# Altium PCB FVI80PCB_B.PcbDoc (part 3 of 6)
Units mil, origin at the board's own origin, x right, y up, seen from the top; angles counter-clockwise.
Board outline 3540 x 3115 mil, 12 copper layers (Top Layer, Int1(GND), Int2(Signal), Int3(GND), Int4(Signal), Int5 (GND&PW), Int6 (GND&PW), Int7(Signal), Int8(GND), Int9(Signal), Int10(GND), Bottom Layer), stack 77.136 mil thick; 488 components, 321 nets, 1809 pads, 882 vias.
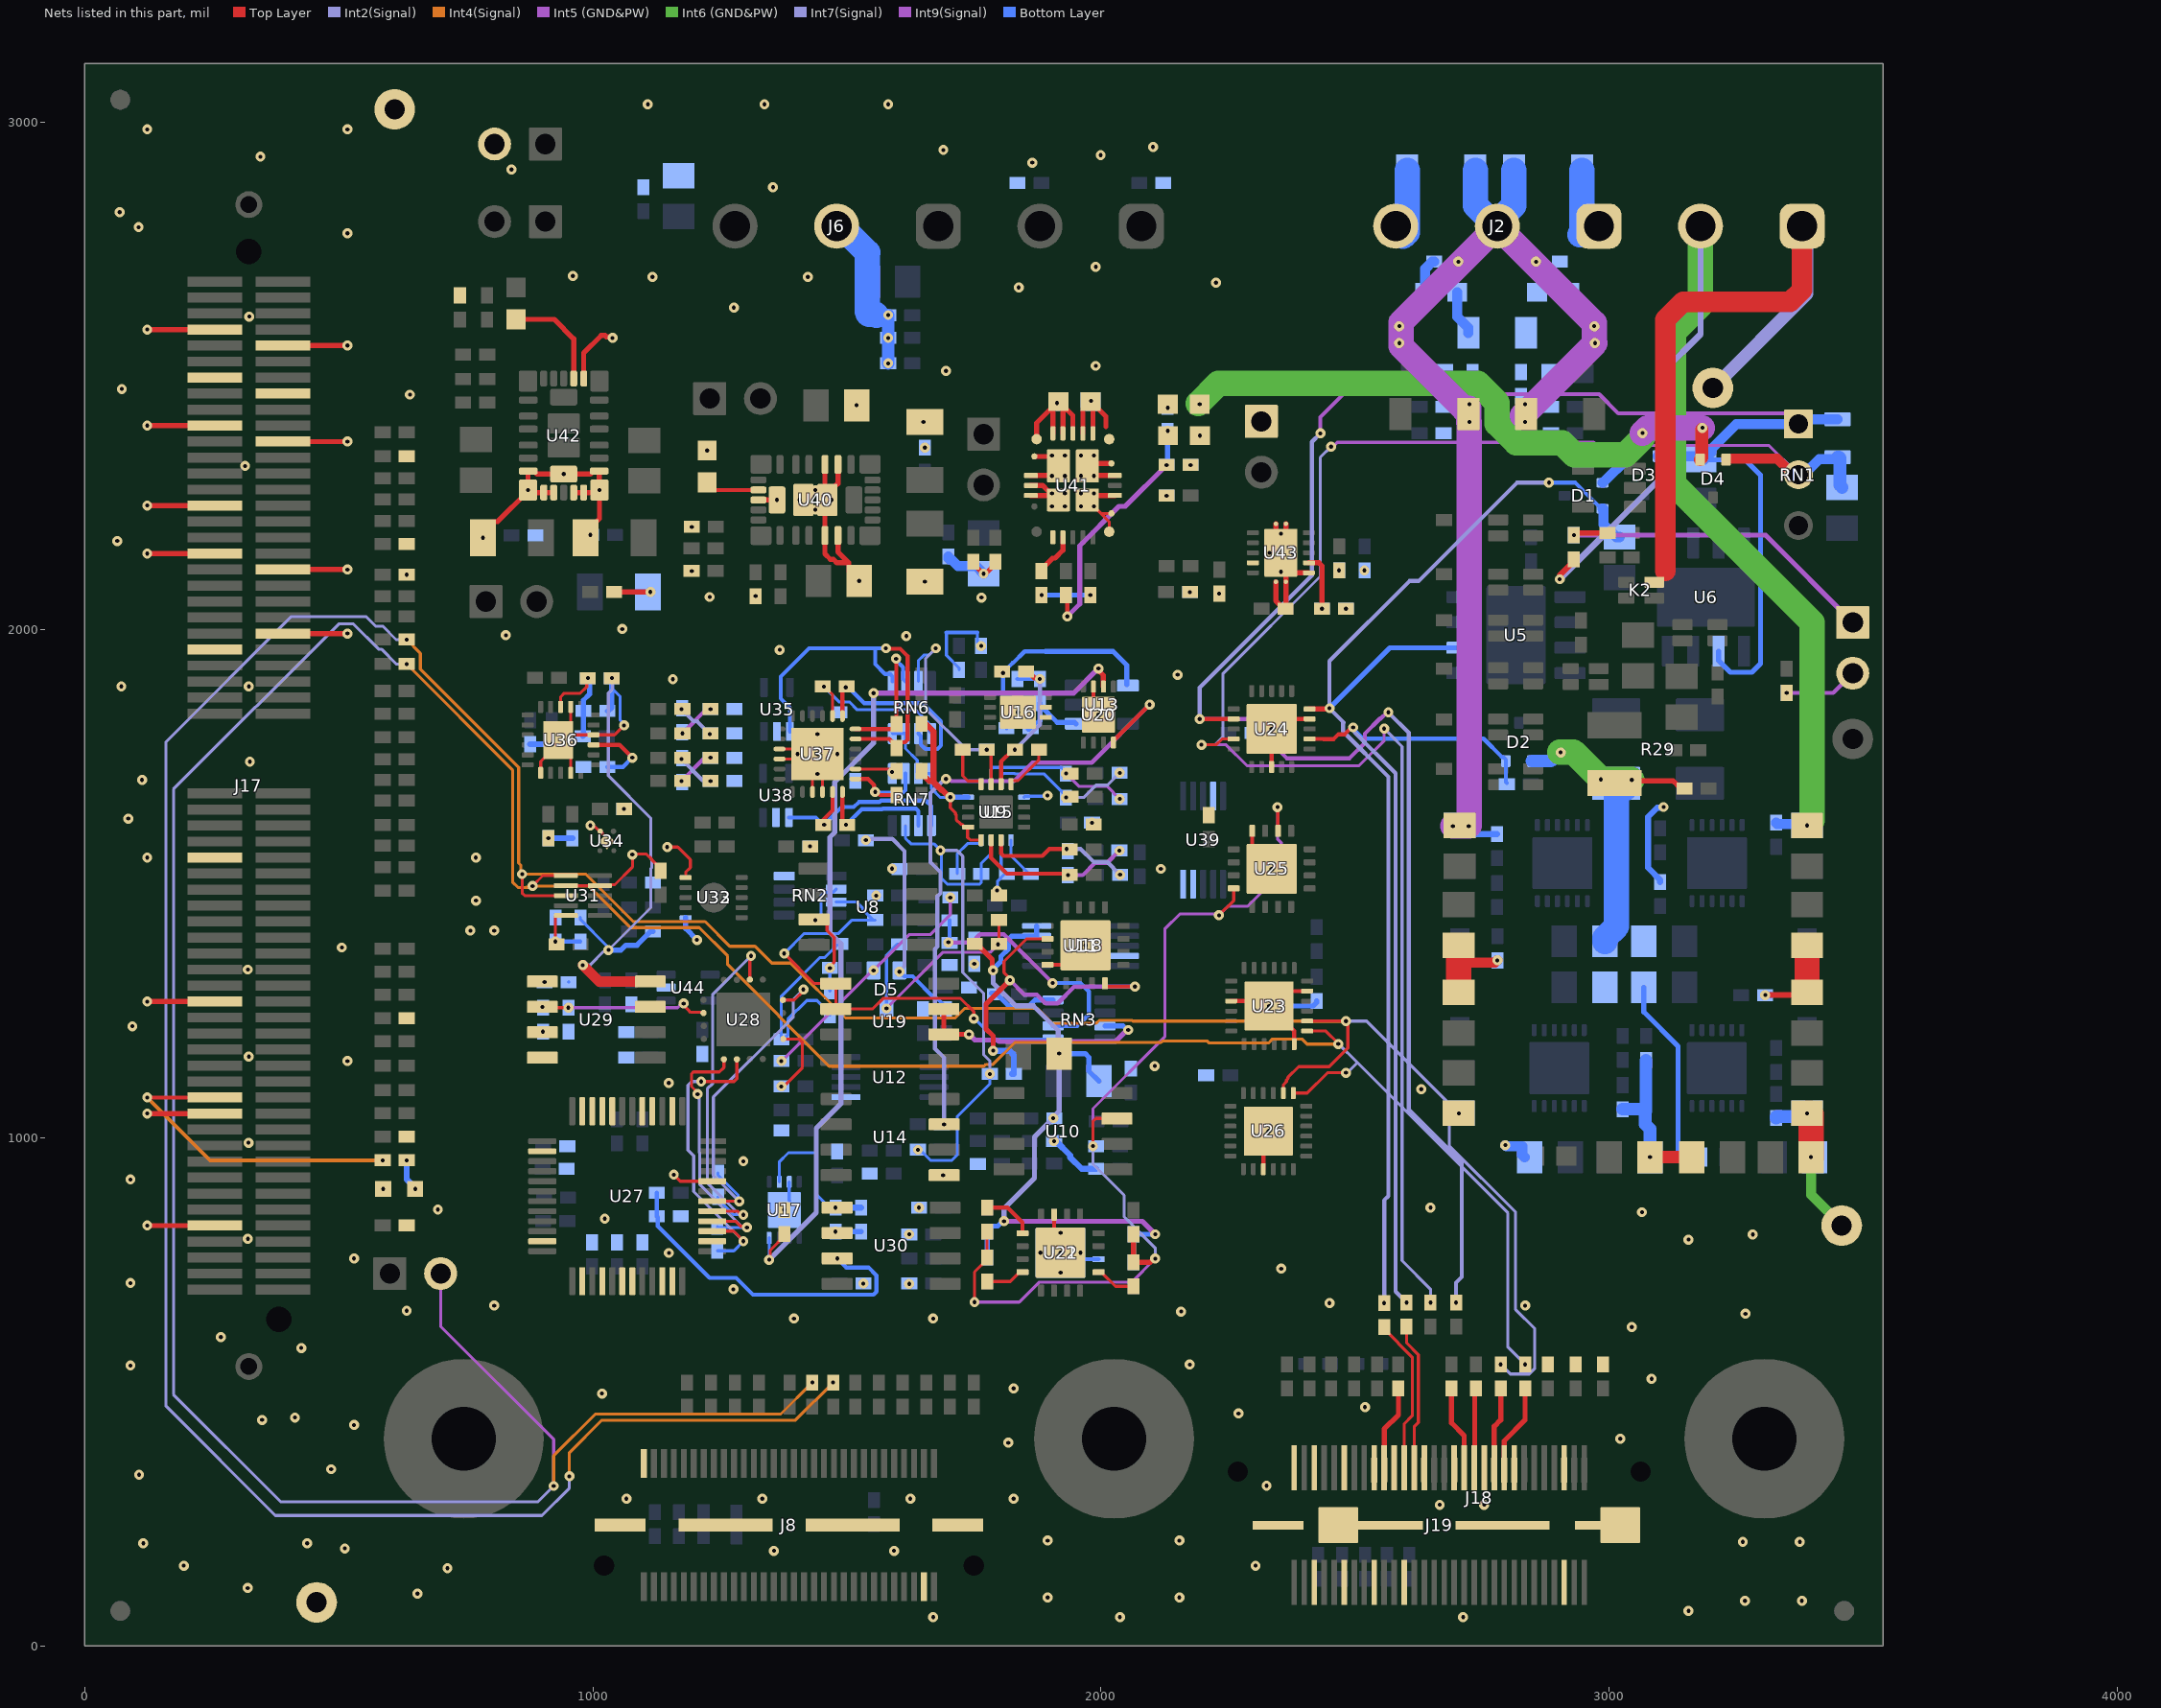
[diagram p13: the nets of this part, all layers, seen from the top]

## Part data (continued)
U24: library part CMP-0120407-1, "36 V, Low Ron, 2:1, 4 Channel Precision Switches with 1.8 V Logic", Digikey Part Number=296-TMUX6234RRQRCT-ND, Manufacturer="Texas Instruments", Max Supply Voltage=36V, Min Supply Voltage=4.5V, Mouser Part Number=595-TMUX6234RRQR, Nominal Supply Current=65uA, On State Resistance=3.6Ω, Operating Temperature Range="-40°C to +125°C"
U27: library part CMP-0093014-3, "20-Bit, Low-Noise, Ultra-Low Harmonic Distortion, FastSettling, High-Voltage Output, Digital-to-Analog Converter (DAC), TQFP48", Manufacturer="Texas Instruments", Max Supply Voltage=5.5V, Min Supply Voltage=1.7V, Operating Temperature Range="-40°C to +125°C"
U28: library part CMP-0126090-1, "Zero-Drift Amplifier 4 Circuit Rail-to-Rail 16-WQFN (4x4)", Input Bias Current=100pA, Input Offset Voltage=1uV, Manufacturer="Texas Instruments", Max Dual Supply Voltage=18V, Max Supply Voltage=36V, Min Dual Supply Voltage=2.25V, Min Supply Voltage=4.5V, Mouser Part Number=595-OPA4187IRUMR, Nominal Supply Current=100uA, Operating Temperature Range="-40°C to +125°C", Output Current Per Channel=30mA, Voltage Gain=160dB
U29: library part CMP-0123003-1, "0.8ppm/°C drift (max), 0.11ppmp-p 1/f noise, 380μA current precision voltage reference", Digikey Part Number=296-REF54410CDRTR-ND, Manufacturer="Texas Instruments", Max Supply Voltage=18V, Min Supply Voltage=4.346V, Mouser Part Number=595-REF54410CDR, Nominal Supply Current=260uA, Operating Temperature Range="0°C to +70°C", Output Voltage=4.096V
U31: library part CMP-0860933-1, "DAC80502DRX, DRX0010A (WSON-10)", Alternate Manufacturer="Texas Instruments"
U32 U33: library part CMP-0126256-1, "High-precision (40µV offset), 2-MHz, 88dB CMRR, low-power, e-trim difference amplifier 10-VSON -40 to 125", Digikey Part Number=296-INA592IDRCRTR-ND, Input Offset Voltage=14uV, Manufacturer="Texas Instruments", Max Dual Supply Voltage=18V, Max Supply Voltage=36V, Min Dual Supply Voltage=2.25V, Min Supply Voltage=4.5V, Mouser Part Number=595-INA592IDRCR, Nominal Supply Current=1.1mA, Operating Temperature Range="-40°C to +125°C", Output Current Per Channel=65mA, Voltage Gain=1/2V/V
U34: library part CMP-0123489-1, "Linear Voltage Regulator IC Positive Fixed 1 Output 300mA 4-X2SON (1x1)", Digikey Part Number=296-TPS7A2018PDQNRCT-ND, Dropout Voltage=200mV, Manufacturer="Texas Instruments", Max Supply Voltage=6V, Min Supply Voltage=2.1V, Mouser Part Number=595-TPS7A2018PDQNR, Nominal Supply Current=6.5uA, Operating Temperature Range="-40°C to +125°C", Output Voltage=1.8V
U35 U38 U44: library part CMP-0126581-1, "Standard (General Purpose) Amplifier 1 Circuit Push-Pull, Rail-to-Rail SC-70-5", Digikey Part Number=296-OPA397DCKRCT-ND, Input Bias Current=0.01pA, Input Offset Voltage=10uV, Manufacturer="Texas Instruments", Max Dual Supply Voltage=2.75V, Max Supply Voltage=5.5V, Min Dual Supply Voltage=850mV, Min Supply Voltage=1.7V, Mouser Part Number=595-OPA397DCKR, Nominal Supply Current=1.22mA, Operating Temperature Range="-40°C to +125°C", Output Current Per Channel=65mA, Voltage Gain=132dB
U36: library part CMP-0121626-2, "Dual, Simultaneous-Sampling, 16-Bit, 5 MSPS SAR ADC, VQFN-HR22", Manufacturer="Texas Instruments", Max Supply Voltage=5.25V, Min Supply Voltage=1.75V, Operating Temperature Range="-40°C to +125°C"
U37: library part CMP-0014032-1, "Low-Noise, Precision, 150-MHz, Fully Differential Amplifier, RTW0024A (WQFN-24)", Alternate Manufacturer="Texas Instruments", Alternate PartNumber=THS4552IRTWT
U40 U42: library part CMP-0090663-2, "TPSM63603 Cruzline Power Module", Manufacturer="Texas Instruments", Max Supply Voltage=36V, Min Supply Voltage=3V, Nominal Supply Current=9uA, Operating Temperature Range="-40°C to +125°C", Output Voltage=1-12V, Switching Frequency=200-2200kHz
U41: library part CMP-0094706-3, "3-V to 17-V, 2-A Low Noise and Low Ripple Buck Converter Module with Integrated Ferrite Bead Filter Compensation", Manufacturer="Texas Instruments", Max Supply Voltage=17V, Min Supply Voltage=3V, Nominal Supply Current=5mA, Operating Temperature Range="-55°C to +125°C", Output Voltage=0.8-5.5V, Switching Frequency=1/2.2MHz
U43: library part CMP-0091022-1, "1-A, Ultra-Low Noise, Ultra-High PSRR, RF Voltage Regulator", Dropout Voltage=210mV, Manufacturer="Texas Instruments", Max Supply Voltage=5.5V, Min Supply Voltage=1.7V, Nominal Supply Current=15-47mA, Operating Temperature Range="-40°C to +150°C", Output Voltage=0.4-5.3V

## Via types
v1: diameter 19.68, hole 7.87, Top Layer to Bottom Layer, tented both sides, 834 vias
v2: diameter 19.68, hole 7.87, Top Layer to Bottom Layer, 39 vias
v3: diameter 23.62, hole 11.81, Top Layer to Bottom Layer, tented both sides, 5 vias
v4: diameter 19.68, hole 7.87, Top Layer to Bottom Layer, tented bottom, 4 vias

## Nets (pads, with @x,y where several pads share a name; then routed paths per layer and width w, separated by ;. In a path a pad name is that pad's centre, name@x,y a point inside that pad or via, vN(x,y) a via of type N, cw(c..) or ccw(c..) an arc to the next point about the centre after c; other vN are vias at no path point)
ClampH_s: D5.1 R49.2 R67.2 | length 485.5
  Int9(Signal) w6: v1(1371.16,1151.5) 1372.61,1151.5 1551.05,1329.93 v1(1552.5,1329.93) 1623.23,1400.67 1664.83,1400.67 1703.62,1439.46 v1(1703.62,1473.26)
ClampL_s: D5.2 R63.2 R76.2 | length 451.2
  Int2(Signal) w8: v1(1537.66,1586.4) 1540.82,1586.4 1543.26,1588.84 1589.6,1588.84 1613.52,1564.92 1613.52,1337.98 1603.68,1328.13 v1(1603.68,1327.45)
  Bottom Layer w8: v1(1603.68,1327.45) 1612.98,1318.15 1629.53,1318.15 1673.49,1274.19 1678.37,1274.19 1695,1257.56 R76.2@1695,1255
ClampSignal: R64.2 RN2.3 RN3.5 U19.1 U19.2 | length 953.2
  Top Layer w6: v1(1376.75,1363.11) 1435.83,1304.02 U19.1@1478.24,1304.02 U19.2@1478.24,1254.02 1550.33,1254.02 1571.14,1274.83 1723.9,1274.83 1750,1248.73 v1(1750,1235) v1@1750,1230
  Bottom Layer w6: v1(1376.75,1363.11) 1416.17,1402.53 1483.85,1402.53 1510.42,1429.1 R64.2@1551.88,1429.1 ; RN2.3@1479.01,1464.4 1519.39,1464.4 1531.23,1452.56 1531.23,1449.75 R64.2@1551.88,1429.1 ; R64.2@1555.82,1429.1 R64.2@1551.88,1429.1 ; v1@1751.11,1236.11 1792.24,1194.99 RN3.5@1905.83,1194.99
Current-: R61.1 U14.7 U20.8 | length 1285.7
  Top Layer w8: U20.8@2024.73,1778.29 2024.73,1785.18 2025.65,1786.1 2028.81,1786.1 2095.71,1853 v1(2096,1853)
  Int2(Signal) w8: v1(1691.55,1026.72) 1691.55,1158.04 1673.54,1176.06 1673.54,1372.14 1678.19,1376.8 1678.19,1475.88 1684.29,1481.98 1684.29,1522.92 1664.44,1542.76 1664.44,1678.73 1692.56,1706.84 v1(1695.24,1706.84)
  Int9(Signal) w8: v1(1695.24,1706.84) 1697.47,1704.6 1703.71,1704.6 1705.76,1702.55 1829.04,1702.55 1865.5,1739 1982,1739 v1(2096,1853)
DA1+: C37.2 U15.9 | length 97.3
  Top Layer w6: U15.9@1823.32,1696.64 1823.32,1701.56 1825.24,1703.48 1837.26,1703.48 1878.07,1744.29 C37.2@1878.07,1764.22
DA1-: C36.2 U15.12 | length 96.4
  Top Layer w6: C36.2@1728.2,1764.22 1728.2,1713.02 1738.67,1702.55 1762.34,1702.55 1764.26,1700.62 U15.12@1764.26,1696.64
DA2+: C28.2 U9.9 | length 84.5
  Bottom Layer w6: U9.9@1823.32,1586.4 1823.32,1555.25 1858.23,1520.34 C28.2@1862.17,1520.34
DA2-: C19.2 U9.12 | length 100.2
  Bottom Layer w6: C19.2@1717.35,1520.34 1717.35,1559.58 1737.33,1579.56 1762.34,1579.56 1764.26,1581.48 U9.12@1764.26,1586.4
Error: R54.2 R80.2 R82.2 R86.1 R107.1 R108.1 R109.1 R112.2 U11.9 U11.10 | length 1450.8
  Top Layer w10: R54.2@1752.09,1381.72 1756.02,1381.72 1786.19,1351.55 1786.19,1331.79 v1(1788.05,1329.93)
  Int2(Signal) w10: v1(1788.05,1329.93) 1788.05,1304.6 1832.36,1260.28 1867,1260.28 1916.11,1211.18 1916.11,1167.94 v1(1917.96,1166.09) 1917.96,1053.2 1906.33,1041.57 v1(1906.33,1038.95) 1869.22,1001.83 1869.22,921.22 1809.5,861.5 v1(1809.5,836.18)
  Int9(Signal) w10: v1(1809.5,836.18) 2081.39,836.18 v1(2107.06,810.51)
  Bottom Layer w10: R109.1@1776.09,764.9 1776.26,765.06 1776.26,815.53 R108.1@1776.42,815.69 1776.42,819.63 1783.23,826.44 1797.13,826.44 1806.88,836.18 v1(1809.5,836.18) ; v1(1788.05,1329.93) 1788.05,1332.55 1803.35,1347.86 1803.35,1357.54 1818.2,1372.4 1818.2,1391.12 1824.06,1396.98 1872.68,1396.98 U11.9@1873.59,1397.89 U11.10@1873.59,1417.57 ; v1(1917.96,1166.09) 1969.18,1166.09 1976.48,1158.78 1976.48,1131.78 R80.2@1996.48,1111.78 ; R112.2@2064.51,755.52 R107.1@2064.51,810.55 2064.55,810.51 v1(2107.06,810.51)
Force_signal_external_Sh: J18.2 J19.20 R198.2 | length 167.9
  Top Layer w10: J19.20@2557.73,350.8 2557.73,427.12 2585.62,455 R198.2@2585.62,507.1
GangForce: R100.2 U17.8 U20.2 | length 1827.3
  Top Layer w6: v1(1347.22,760.3) 1349.27,762.36 1349.27,779.15 1377.4,807.27 R100.2@1377.4,811.21
  Top Layer w10: v1(1995.2,1924.23) 1995.2,1920.53 2005.05,1910.69 U20.2@2005.05,1888.53
  Int2(Signal) w10: v1(1347.22,760.3) 1439.91,853 1439.91,1019.03 1488.23,1067.34 1488.23,1383.12 1466.8,1404.56 1466.8,1592.26 1476.19,1601.65 1476.19,1700.78 1552.5,1777.09 v1(1552.5,1875.84)
  Int9(Signal) w10: v1(1552.5,1875.84) 1946.81,1875.84 v1(1995.2,1924.23)
  Bottom Layer w6: v1(1347.22,760.3) U17.8@1347.22,803.34
GNDA: C1.1 C2.1 C3.1 C4.1 C5.1 C6.1 C7.1 C8.1 C9.2 C10.2 C11.2 C12.2 C13.2 C14.1 C15.1 C16.1 C17.1 C18.1 C140.2 C141.2 C142.1 C143.1 J1.2 J2.2 R4.1 R5.1 R6.1 R12.1 R13.1 R14.1 R15.1 R16.1 R17.1 R32.1 R72.1 R73.1 R74.1 R85.1 R96.1 R97.1 R98.1 R101.1 R102.1 TP3.1 | length 5640.5
  Top Layer w12: v1(2903,2100) 2904.47,2101.47 2904.47,2108.91 2931,2135.44 R32.1@2931,2139.38 ; v1(3307.62,1281.42) 3384.45,1281.42 R12.1@3390,1286.97
  Top Layer w20: 2704.42,1345.16 2775.84,1345.16 v1(2780.34,1349.66)
  Top Layer w25: v1(3080.72,962.37) R16.1@3163.34,962.37
  Top Layer w50: R85.1@2704.42,1286.97 2704.42,1345.16 R101.1@2704.42,1379.16 ; v1(3390,1048.52) 3396.5,1048.52 3397.81,1047.21 v1(3397.81,962.37) ; R12.1@3390,1286.97 R73.1@3390,1379.16
  Int5 (GND&PW) w50: v1(2692.82,1614) v1(2724,1614) ; 2715,2435 2591,2559 2591,2605.66 J2.2@2780.34,2795 2971,2604.34 v1@2971,2564.69 ; v1@2724,2409.48 v1@2724,2436 ; v1@2725.28,1615.28 v1(2725.28,2409.48) ; 2830,2422.17 v1(2972.52,2564.69)
  Int6 (GND&PW) w20: v1(3397.81,962.37) 3397.81,888.13 TP3.1@3458.22,827.72
  Int6 (GND&PW) w50: J1.2@3180,2795 3180,2639.06 3127,2586.06 3127,2288 3400,2015 3400,1625.25 v1(3390,1615.25)
  Int2(Signal) w12: v1(2903,2100) 3107,2304 3107,2509 3180.34,2582.34 J1.2@3180.34,2795
  Bottom Layer w12: R102.1@2715.79,1605.79 2723.46,1598.12 C4.1@2779.54,1598.12 ; C2.1@3100.81,1504.08 3100.81,1508.02 3077,1531.83 3077,1632.03 3095.07,1650.1 3106.03,1650.1 v1(3107.5,1651.57)
  Bottom Layer w20: v1(2796,986) 2798.13,983.87 2829.37,983.87 2829.37,966.63 R6.1@2834,962 ; C8.1@3329,1620.62 3329,1619.74 3330.81,1617.93 3387.31,1617.93 v1(3390,1615.25)
  Bottom Layer w25: C7.1@3027,1056.69 3073,1056.69 ; C5.1@3073,1153.38 3073,1056.69 ; v1(3080.72,962.37) 3080.72,1017.77 3071.48,1027.01 3071.48,1050.49 3073,1052.01 3073,1056.69 ; C3.1@3329,1039.2 3329,1041.76 3329.69,1042.44 3383.93,1042.44 v1(3390,1048.52)
  Bottom Layer w50: C14.1@2736.93,2905 2736.93,2836.07 2777.99,2795 J2.2@2780.34,2795 2780.34,2803.34 2813.07,2836.07 C9.2@2813.07,2905
  other v1: 2704.42,1048.52 2834.72,2409.48 2725.28,2444.25 2834.72,2444.25 2587.48,2564.69 2587.48,2598.15 2971,2598.15 2703.62,2725 2856.38,2725
GNDB: C20.1 C21.1 C22.1 C23.1 C24.1 C25.1 C26.1 C28.1 C29.2 C31.2 C32.1 C33.2 C34.2 C35.1 C42.1 C43.1 C44.1 C45.2 C47.2 C48.1 C49.1 C50.2 C51.2 C53.1 C54.2 C55.1 C57.1 C58.2 C59.1 C60.1 C61.1 C62.1 C63.1 C64.1 C65.2 C66.2 C67.2 C68.2 C69.2 C70.2 C71.1 C72.1 C75.2 C76.1 C77.2 C78.1 C79.2 C80.1 C85.1 C86.2 C88.1 C89.1 C90.2 C91.2 C92.1 C93.2 C95.2 C97.1 C99.2 C100.2 C101.2 C102.2 C103.2 C104.2 C105.2 C106.2 C107.2 C108.2 C109.2 C110.2 C111.2 C112.2 C113.2 C114.2 C115.2 C116.2 C117.2 C118.2 C119.2 C120.1 C122.1 C123.1 C124.1 C125.1 C126.1 C127.1 C128.2 C129.2 C130.2 C131.2 C132.1 C133.2 C134.1 C137.2 C138.2 C139.2 C144.1 C145.1 C146.1 C147.1 C148.2 C149.2 C150.2 D1.1 D2.1 D3.1 D4.2 D8.1 J5.2 J6.2 J7.2 J8.3 J8.60 J8.MP1 J8.MP2 J8.MP3 J8.MP4 J17.7 J17.10 J17.13 J17.16 J17.19 J17.22 J17.29 J17.35 J17.38 J17.46 J17.47 J17.65 J17.83 J17.97 J17.111 J18.1 J18.3 J18.6 J18.9 J18.12 J18.15 J18.20 J18.MP1 J18.MP2 J19.2 J19.5 J19.6 J19.11 J19.12 J19.17 J19.18 J19.22 J19.23 J19.28 J19.34 J19.40 J19.46 J19.55 J19.56 J19.MP1 J19.MP2 J19.MP3 J19.MP4 R1.2 R2.2 R8.2 R18.2 R19.2 R24.1 R27.2 R29.I2 R48.1 R57.1 R66.2 R69.2 R70.2 R77.2 R78.2 R79.1 R90.1 R100.1 R104.1 R110.1 R113.2 R122.2 R127.1 R142.1 R149.1 R150.2 R152.2 R153.2 R154.1 R156.2 R158.2 R161.1 R164.1 R168.1 R234.2 RN2.8 RN3.8 RN6.7 RN6.8 RN7.7 RN7.8 TP5.1 TP6.1 U9.5 U9.10 U9.16 U11.4 U12.1 U14.5 U15.1 U15.16 U16.2 U16.3 U16.9 U17.3 U17.9 U18.4 U18.17 U20.3 U20.9 U21.3 U21.17 U22.3 U22.17 U23.9 U23.18 U23.23 U23.25 U24.4 U24.18 U24.21 U25.4 U25.17 U26.9 U26.25 U27.2 U27.8 U27.14 U27.16 U27.17 U27.20 U27.21 U27.22 U27.23 U27.26 U27.35 U27.38 U27.40 U27.42 U27.43 U27.46 U27.47 U28.9 U29.3 U29.4 U29.7 U29.8 U31.4 U31.7 U32.6 U33.6 U34.2 U34.5 U35.2 U36.4 U36.8 U36.18 U36.21 U36.23 U37.15 U37.16 U37.21 U37.22 U37.25 U38.2 U39.4 U39.9 U39.10 U40.5 U40.6 U40.16 U40.17 U40.24 U40.27 U40.28 U40.29 U41.1 U41.2 U41.3 U41.5 U41.6 U41.7 U41.8 U41.9 U41.16 U41.17 U41.20 U41.25 U41.26 U41.28 U42.7 U42.8 U42.9 U42.10 U42.12 U42.13 U42.14 U42.15 U42.22 U42.30 U43.4 U43.6 U43.11 U44.2 | length 11472
  Top Layer w6: U36.18@897.43,1718.68 897.43,1741.34 931.96,1775.87 U36.23@931.96,1783.64 ; U31.7@946.9,1496.88 U31.4@1013.83,1496.88 1015.56,1498.6 1043.47,1498.6 1078.17,1533.31 1078.17,1557.38 v1(1077.72,1557.83) 1078.92,1559.03 1105.21,1559.03 1116.25,1547.99 1116.25,1547.04 1133.43,1529.86 C62.1@1133.43,1525.93 ; U36.21@956.48,1718.68 956.45,1759.15 U36.23@931.96,1783.64 ; U36.8@956.48,1848.6 956.45,1808.13 U36.23@941.8,1793.48 ; v1(995.22,1615.08) 997.84,1612.46 1004.65,1612.46 1013.41,1603.7 U34.2@1014.76,1603.7 1027.76,1590.71 U34.5@1027.76,1583.82 ; v1(1061.52,1812.34) 1042.66,1793.48 U36.4@1001.76,1793.48 U36.23@941.8,1793.48 ; v1(1146.44,1572.74) 1167.17,1572.74 1191.92,1547.99 1191.92,1532.38 1182.81,1523.26 U33.6@1182.81,1512.63 ; v1(1159.41,927.72) 1172.21,914.92 U27.8@1235.2,914.92 ; U37.16@1367.46,1746.13 1432.42,1746.13 v2(1442.27,1755.97) ; U37.15@1367.46,1765.81 1394.09,1765.81 1402.9,1757 v2(1402.9,1755.97) ; v1@1374.11,1100.14 1412.74,1138.77 1412.74,1187.65 1405.41,1194.99 U28.9@1374.82,1194.99 ; U37.21@1432.42,1681.17 1432.42,1707.79 1441.24,1716.6 v2(1442.27,1716.6) 1443.3,1716.6 1452.11,1707.79 U37.22@1452.11,1681.17 ; v1(1703.62,1671.05) 1703.62,1649.94 1714.08,1639.48 1714.08,1637.07 1715.26,1635.89 1715.26,1626.78 1724.29,1617.76 1726.02,1617.76 1731.78,1611.99 U15.16@1738.67,1611.99 1737.69,1611.01 1737.69,1591.69 1742.97,1586.4 U15.1@1764.26,1586.4 ; U41.25@1973.55,2256.04 v1(1986.34,2243.25) 2000.12,2229.47 ; U41.1@2016.43,2193.48 2016.43,2213.17 2000.12,2229.47 ; U41.2@2020.79,2229.47 2000.12,2229.47 ; U36.23@931.96,1783.64 U36.23@941.8,1793.48
  Top Layer w8: U18.4@1895,1340.8 1931.42,1340.8 v1(1969.8,1379.19) ; U22.3@1907.84,849.01 1907.84,819.42 1913.68,813.58 v1(1920.63,813.58) ; U20.3@1985.36,1888.53 1985.36,1843.25 v1(1995.2,1833.41) ; U23.9@2256.48,1269.61 2321.44,1269.61 v1(2331.28,1259.76) ; U25.4@2297.8,1604.61 2297.8,1568.19 v1(2336.19,1529.81) ; U26.9@2319.86,938.75 2319.86,1003.71 v1(2329.7,1013.55) ; U24.18@2336.19,1730.38 v1(2336.19,1805.18) 2355.87,1824.87 U24.4@2410.99,1824.87 ; U23.18@2380.49,1184.96 2380.49,1210.55 v1(2331.28,1259.76) ; U23.23@2406.08,1289.29 2360.81,1289.29 v1(2331.28,1259.76)
  Top Layer w10: v1(123,827.68) J17.111@256.07,827.68 ; v1(123,1048.15) J17.97@256.07,1048.15 ; v1(123,1268.62) J17.83@256.07,1268.62 ; v1(123,2150.51) J17.35@256.07,2150.51 ; v1(123,2245) J17.29@256.07,2245 ; v1(123,2402.48) J17.19@256.07,2402.48 ; v1(123,2591.46) J17.7@256.07,2591.46 ; J17.46@389.93,1993.03 v1(517,1993.03) ; J17.38@389.93,2119.02 v1(517,2119.02) ; J17.22@389.93,2370.99 v1(517,2370.99) ; J17.10@389.93,2559.96 v1(517,2559.96) ; v1(783.58,2181.67) 783.58,2192.5 804.17,2213.09 812.41,2213.09 872.47,2273.15 v1(872.47,2275.51) ; U42.10@923.1,2270.59 U42.9@903.42,2270.59 877.39,2270.59 v1(872.47,2275.51) ; U42.12@962.47,2270.59 U42.13@982.16,2270.59 1008.18,2270.59 v1(1013.1,2275.51) ; U42.22@982.16,2495 982.16,2545.53 1016.63,2580 1023.91,2580 1027.06,2576.85 1036.93,2576.85 v1(1038.78,2575) ; C126.1@985.77,2181.24 985.77,2192.07 1013.1,2219.4 v1(1013.1,2275.51) ; C124.1@1041.88,2075 v1(1113.36,2075) ; U40.24@1326.05,2256.04 v2(1362.46,2256.04) ; U40.17@1456.95,2325.92 1456.95,2268.84 1461.87,2263.92 1461.87,2267.85 1482.54,2288.52 U40.16@1482.54,2325.92 ; v2(1469.75,2256.04) 1456.95,2243.25 U40.5@1456.95,2186.16 1456.95,2149.85 1467.65,2139.15 1473.71,2139.15 1480.52,2132.35 1504.16,2132.35 ; U40.6@1482.54,2186.16 1482.54,2153.96 1504.16,2132.35 ; v1(1524.16,2096.65) 1504.16,2116.65 1504.16,2132.35 ; C105.2@1748.8,2134.51 1748.8,2130.57 1768.49,2110.89 v1(1769.3,2110.89) 1771.16,2112.74 1774.74,2112.74 1792.58,2130.57 C106.2@1792.58,2134.51 ; U41.17@1862.33,2264.9 1899.73,2264.9 v1(1903.67,2268.84) 1898.83,2273.68 1896.27,2273.68 1885.37,2284.59 U41.16@1862.33,2284.59 ; U41.9@1964.69,2386.95 1964.69,2435.77 1978.63,2449.71 C112.2@1979.62,2449.71 ; U41.26@1973.55,2322.97 1978.47,2327.89 U41.6@2020.79,2327.89 ; U41.8@1984.38,2386.95 1984.38,2444.95 C112.2@1979.62,2449.71 ; v1(1986.34,2268.84) 1990.28,2264.9 U41.3@2027.68,2264.9 ; v1(1986.34,2303.29) 1987.33,2304.27 U41.5@2027.68,2304.27 ; 2009.97,2400.73 2009.97,2420.35 1980.6,2449.71 C112.2@1979.62,2449.71 ; v4(2331.67,2152.03) 2344.47,2164.83 U43.11@2344.47,2209.04 ; U43.11@2344.47,2094.94 2344.47,2057.37 2359.81,2042.03 R156.2@2367.68,2042.03 ; v4(2354.31,2114.63) 2359.31,2114.63 U43.11@2361.28,2112.66 ; U43.11@2364.15,2209.12 2364.15,2164.83 v4(2376.95,2152.03) ; R156.2@2367.36,2042.03 2364.15,2045.24 2364.15,2109.79 U43.11@2361.28,2112.66 ; U43.6@2409.43,2112.66 U43.11@2361.28,2112.66 ; v1(3045,1705) 3047.16,1702.84 3126.58,1702.84 3134.62,1694.8 3141.71,1694.8 R27.2@3148.52,1687.99 ; v1(872.47,2275.51) 872.69,2275.73 872.69,2312.7 884.93,2312.7 890.62,2307.01 v2(942.79,2307.01) 994.95,2307.01 1000.86,2312.91 U42.15@1012.67,2312.91 1012.89,2312.7 1012.89,2275.73 v1(1013.1,2275.51)
  Top Layer w12: C34.2@1646.8,1815.05 1649.51,1812.34 1658.35,1812.34 1670.61,1800.08 1670.61,1705.1 1668.35,1702.83 ; C33.2@1650.18,1725.71 C33.2@1646.8,1722.33 1646.8,1718.39 1662.36,1702.83 1668.35,1702.83 ; v1(1703.62,1671.05) 1701.54,1671.05 1687.6,1685 1686.19,1685 1668.35,1702.83
  Top Layer w20: v1(980.22,1340.29) 1012.5,1308.02 U29.4@1113.36,1308.02
  Top Layer w25: D4.2@3179.41,2335.4 3183,2338.99 v1@3183,2395
  Int5 (GND&PW) w50: v1(3066,2387.6) 3076.4,2398 v1(3184,2398)
  Int6 (GND&PW) w50: v1@2192,2446 2231.1,2485.1 2742.19,2485.1 2780,2447.29 2780,2406.45 2817.81,2368.64 2907.99,2368.64 2931.47,2345.16 3032.92,2345.16 3066,2378.24 v1(3066,2387.6) ; v1@2903,1760 2930,1760 v1(2984,1706) 3044,1706 v1(3045,1705)
  Int2(Signal) w6: v1(980.22,1340.29) 980.52,1340.58 994.58,1340.58 1021.38,1367.38 1028.22,1367.38 1114.18,1453.34 1114.18,1530.31 1116.25,1532.38 1116.25,1547.99 1114.18,1550.06 1114.18,1629.67 1030.68,1713.17 1030.68,1875.64 1038.63,1883.59 1038.63,1904.27 v1(1037.47,1905.44)
  Bottom Layer w6: C51.2@952.33,1306.88 C51.2@952.98,1307.52 ; C57.1@975.54,1434.09 975.54,1430.15 1028.22,1377.48 1028.22,1372.62 v1(1030.84,1370) ; 1037.47,1885.58 1053.83,1869.22 1053.83,1822.7 1061.52,1815.01 v1(1061.52,1812.34) ; v1(1037.47,1905.44) C91.2@1041.41,1905.44 ; U17.3@1386.59,913.57 1386.59,877.41 U17.9@1388,876 ; C35.1@1466.57,1241.93 1466.57,1245.86 1441.59,1270.84 1421.2,1270.84 1383.91,1233.55 1383.91,1202.81 1375.09,1194 C68.2@1371.16,1194 1371.16,1279.22 1447.32,1355.38 1456.88,1355.38 1483.22,1381.72 C69.2@1487.16,1381.72 ; RN6.8@1589.79,1796.35 RN6.7@1615.38,1796.35 1615.38,1766.68 1638.5,1743.56 1638.5,1719.88 RN7.7@1640.97,1717.41 RN7.8@1666.57,1717.41 1666.57,1687.89 1684.29,1670.17 1702.74,1670.17 v1(1703.62,1671.05) ; 1696,1995 1696,1950.31 1721,1925.32 C72.1@1721,1921.38 ; 1757.21,1995 1757.21,1975.68 v1(1764.26,1968.62) ; v1(1795.65,1487.26) 1796.76,1488.37 1796.76,1506.1 1810.99,1520.34 1812.45,1520.34 1803.63,1529.15 U9.10@1803.63,1586.4 ; U9.5@1848.91,1671.05 1850.52,1672.66 1893.43,1672.66 v1(1895.04,1674.28)
  Bottom Layer w8: 1696,1995 1757.21,1995 ; v1(1920.63,774.21) 1933.43,761.41 U21.3@1995.44,761.41
  Bottom Layer w10: C93.2@1028.85,1840.44 1030.66,1840.44 1037.47,1847.25 v1(1037.47,1905.44) ; v1(1030.84,1370) 1030.9,1370.06 1055.68,1370.06 1064.98,1379.36 1087.14,1379.36 1114.51,1406.73 C64.1@1118.45,1406.73 ; U32.6@1182.81,1433.89 1182.81,1412.53 1205,1390.33 v1(1205,1390) ; v1(1703.62,1671.05) U9.16@1738.67,1671.05 ; C29.2@1785,1285 1793.37,1285 1818.05,1260.31 1858.85,1260.31 1870.16,1271.62 1905.69,1271.62 RN3.8@1905.83,1271.76 ; C32.1@1835.97,1856.38 1836.38,1855.97 1836.38,1838.27 v1(1836.79,1837.86) ; v1(1883.39,2068.7) v1(1979.32,2068.7) ; v1@2333,1260 2333.24,1259.76 2417.74,1259.76 2424.55,1266.58 C44.1@2424.55,1270.02 ; v1@2333.02,1532.97 v1@2335.97,1532.97 ; R1.2@3068.52,1296.75 3068.52,1248.21 3136,1180.74 3136,974.9 3147.26,963.64 3170.88,963.64 R8.2@3172.15,962.37
  Bottom Layer w12: C75.2@877.04,1775.15 v1(919.51,1775.15) ; C78.1@912.81,1590.25 R142.1@960.04,1590.25 ; v1(1907.86,993.67) 1911.8,993.67 1939.97,965.5 1939.97,961.56 1962.33,939.2 R104.1@1990.39,939.2
  Bottom Layer w20: C104.2@1699.79,2144.82 1699.79,2140.88 1701.6,2139.07 1705.54,2139.07 1718.72,2125.89 1754.3,2125.89 v1(1769.3,2110.89) ; D1.1@2987.57,2289.93 2988.63,2289.93 3039.3,2340.59 3043.66,2340.59 3044.41,2341.34 D3.1@3044.41,2342.4 3044.41,2366.01 v1(3066,2387.6)
  Bottom Layer w25: v1(1581.38,2525) v1(1581.38,2575) v1(1581.38,2620) ; D2.1@2848.32,1742.13 2886.13,1742.13 v1@2902,1758
  Bottom Layer w50: J6.2@1480,2795 1489,2795 1541,2743 1540,2742 C107.2@1540,2685.95 1540,2630.99 ccw(c1553.84,2630.99) 1544.05,2621.21 1555.27,2621.21 cw(c1555.27,2617.08) 1558.18,2620 ; R19.2@2992.15,1387.25 2992.15,1393.75 3015,1416.6 R29.I2@3015,1682 ; R29.I2@3031,1687.99 R29.I2@3031,1693
  other v1: 1670.04,56.87 2037.63,56.87 2713,56.87 3156.76,69 3267.8,88.79 3379.91,88.79 1895.27,95.48 2154.69,95.48 655,103 320.84,114 714,153 195.07,158 2304.51,158 1356.5,187.46 1592.9,187.46 512,192 115.26,202.12 437.98,202.12 3263.51,205.02 3375.63,205.02 1895.27,207.6 2154.69,207.6 2667,278 2754.58,278 1066.11,290 1333.57,290 1625,290 1828.34,290 2326.13,315.5 107,337 485,348 1818,400 3022.3,408 530,435 349,445 413.71,449.77 2270.98,457.77 2520,470.13 1018,497 1828.34,507.1 3084,526 90,552 2175,554 426.27,586.68 267.8,608 3045.08,627.72 1395.9,644.7 1670.04,644.7 3268.57,654 2158,658.42 633.74,660 806,670 2835.14,670 2450,674.96 1276.67,702.1 1622.82,712.76 90,714.35 1532.64,713.55 1920.63,734.84 1920.63,734.84 2354.9,742.68 530,762.89 1149.8,773.78 1881.26,774.21 1881.26,774.21 1920.63,774.21 1960,774.21 1960,774.21 3156.76,800 321.05,801.43 3283.18,810 1622.8,810.51 1920.63,813.58 1023.59,841.1 3065,854 1376.75,858.45 695,859.02 1642.09,862.89 2648.84,862.89 587.5,899.83 90,918.27 1689.47,926.33 1296.35,954.29 322.51,990.51 2630.61,1096.1 1371.16,1101.5 1149.68,1108.41 2106,1141.76 517,1151.5 322.98,1160.23 901.83,1209.39 93.77,1219.89 321.05,1331.62 1750.88,1342.78 506,1375 759,1408.3 806,1408.3 770,1467.42 1557.79,1477.19 1589,1530.17 2118,1529.81 123,1552 769.77,1552 1427.83,1573.88 912.78,1590.28 1982.54,1620.51 85.62,1628.72 1061.52,1647.79 112.91,1705 325,1740.86 2905,1759 72.04,1889.04 322.87,1889.04 1157.55,1903.21 2151,1912 1368,1961 1617,1988 828.95,1989.67 1058,2002 2482.41,2042.03 1765,2064 1230,2065 1320.51,2066.61 2233.01,2071.53 2175.43,2074.47 1653.53,2094.94 633.62,2108.97 1194.83,2115.94 2468.79,2117.25 2518.79,2117.25 63.89,2175.17 995.22,2187.14 1194.83,2202.91 1903.67,2243.25 1929.26,2243.25 1960.75,2243.25 2129.38,2264.33 1929.26,2268.84 1960.75,2268.84 1960.75,2303.29 315.6,2323 2176.63,2324.68 1960.75,2343.64 1986.34,2343.64 1225.08,2353.5 1653.53,2359.17 2195.13,2382.62 1650.92,2409.48 1519.39,2442.3 2194.5,2444.25 1980.42,2451.36 640.06,2463.31 72.95,2474.44 1695.24,2510 1989.84,2519.94 323.96,2617.07 1277.55,2634.61 1838.32,2674.45 2226.74,2683.65 1117.54,2695 1423.36,2695 960.89,2697.04 1989.84,2715 517,2780.83 106,2793 68.87,2822.59 1354.66,2871.62 840,2906.69 1864.93,2920 345.78,2931.64 1999.53,2935 1690,2945 2102.56,2950.87 123,2985.59 517,2985.59 1108.25,3035 1337.86,3035 1581.38,3035
  other v2: 1481.64,1755.97 1442.27,1795.34 1438.25,2236.75 1406.76,2256.04 1438.25,2275.33
  other v4: 2354.31,2189.43
I2C_SCL_C2K_Sh: J18.14 J19.44 R189.2 | length 173.4
  Top Layer w10: J19.44@2793.95,350.8 2793.95,403.81 2835.14,445 R189.2@2835.14,507.1
I2C_SCL_IN: J14.2 R175.1 R189.1 R227.1 U23.19 U26.19 U31.6 | length 7219
  Top Layer w6: v1(881.34,1496.04) 901.87,1516.56 U31.6@946.9,1516.56 ; U26.19@2378.92,1088.36 2406,1088.36 2446.16,1128.52 v1(2482.41,1128.52) ; U23.19@2406.08,1210.55 2442.75,1210.55 2467.18,1186.12 v1(2467.18,1184.96)
  Int9(Signal) w6: J14.2@700.5,733.19 700.5,629.22 923,406.72 v1(923,315)
  Int4(Signal) w6: v1(633.62,1933) 842.21,1724.41 842.21,1503.98 853.25,1492.94 868.86,1492.94 869.32,1493.41 ; 869.33,1493.42 878.72,1493.42 v1(881.34,1496.04) 991.71,1496.04 1073.73,1414.01 1209.57,1414.01 1265.3,1358.28 1265.3,1341.37 1465.16,1141.51 1770.29,1141.51 1773.71,1144.93 1787.8,1144.93 1830.98,1188.11 2118.65,1188.11 2121.73,1191.19 2208.97,1191.19 2213.2,1186.97 2329.88,1186.97 2337.91,1195 2395.67,1195 2405.71,1184.96 v1(2467.18,1184.96) ; v1(923,315) 923,374.69 1004.84,456.53 1369.91,456.53 v1(1432,518.62)
  Int7(Signal) w6: v1(633.62,1933) 613.02,1933 583.79,1962.23 578.57,1962.23 528.93,2011.87 499.87,2011.87 174.78,1686.78 174.78,495 385.97,283.81 891.81,283.81 v1(923,315) ; v1(2467.18,1184.96) 2468.34,1184.96 2504.77,1148.53 ; v1(2482.41,1128.52) 2484.76,1128.52 2504.77,1148.53 ; v1(2835.14,554.34) 2801.13,588.35 2801.13,852.17 2504.77,1148.53
I2C_SCL_PW_Sh: J18.11 J19.38 R191.2 | length 157.6
  Top Layer w10: J19.38@2734.9,350.8 2735.8,351.7 2735.8,504.97 R191.2@2737.93,507.1
I2C_SDA_C2K_Sh: J18.13 J19.42 R190.2 | length 161.6
  Top Layer w10: J19.42@2774.27,350.8 2774.27,432.21 2787.06,445 R190.2@2787.06,507.1
I2C_SDA_IN: R173.1 R190.1 R226.1 U23.20 U26.20 U31.8 | length 7142.3
  Top Layer w6: v1(861.05,1519.37) 861.05,1482.16 866.01,1477.19 U31.8@946.9,1477.19 ; U26.20@2359.23,1088.36 2359.23,1104.86 2365.19,1110.82 2365.19,1114.16 2368.23,1117.2 2368.23,1119.31 2389.44,1140.52 2449.38,1140.52 2486.02,1177.16 v1@2486.02,1227.94 ; U23.20@2406.08,1230.24 v1(2482.41,1230.24)
  Int4(Signal) w6: v1(633.62,1981.07) 660.78,1953.92 660.78,1922.81 854.21,1729.38 854.21,1541.21 858.43,1536.99 858.43,1521.99 v1@862.54,1517.88 ; v1(861.05,1519.37) 986.36,1519.37 1079.71,1426.01 1221.12,1426.01 1269.77,1377.36 1319.21,1377.36 1352.31,1344.27 1389.43,1344.27 1497.42,1236.29 1713.33,1236.29 1732.09,1255.05 1875.14,1255.05 1904.03,1226.16 1991.32,1226.16 1996.71,1231.55 2061.67,1231.55 2062.98,1230.24 v1(2482.41,1230.24) ; v1(954,334) 954,380.71 1017.82,444.53 1398.91,444.53 v1(1473,518.62)
  Int7(Signal) w6: v1(633.62,1981.07) 613.02,1981.07 586.52,2007.58 572.42,2007.58 553.58,2026.43 406.42,2026.43 160,1780 160,472 375,257 900,257 954,311 v1(954,334) ; v1(2482.41,1230.24) 2523.12,1230.24 2685.58,1067.78 2685.58,984.69 2816.3,853.97 2816.3,662.2 2853.98,624.51 2853.98,546.54 2842.95,535.5 2805.9,535.5 v1(2787.06,554.34)
I2C_SDA_PW_Sh: J18.10 J19.36 R192.2 | length 166.6
  Top Layer w10: R192.2@2690.3,507.1 2690.3,439.12 2715.21,414.21 J19.36@2715.21,350.8
ISENSE: R51.2 U18.2 U18.8 | length 737.3
  Top Layer w6: v1(1821.06,1310.68) 1821.06,1314.21 1809.5,1325.77 1809.5,1347.69 1853.79,1391.98 U18.2@1895,1391.98 ; U18.8@2008.19,1304.38 2008.19,1300.91 2011.1,1298 v1(2067,1298)
  Top Layer w10: v1(1788.05,1171.82) 1788.05,1200.85 1774.11,1214.79 1774.11,1263.73 v1(1821.06,1310.68)
  Int9(Signal) w8: v1(1821.06,1310.68) 1849.69,1282.05 1874.28,1282.05 1891.33,1265 1915,1265 1948,1298 v1(2067,1298)
  Bottom Layer w12: v1(1788.05,1171.82) 1820.53,1171.82 1828.76,1163.6 R51.2@1828.76,1126.09 R51.2@1824.82,1126.09
Isense_N_LV_Sh: J18.4 J19.24 R196.2 | length 306.4
  Top Layer w6: R196.2@2557.73,627.72 2557.73,623.78 2613,568.51 2613,453 2597.1,437.1 J19.24@2597.1,350.8
Isense_P_LV_Sh: J18.5 J19.26 R195.2 | length 291
  Top Layer w6: R195.2@2601.72,628.72 2601.72,596.76 2625,573.48 2625,440 2616.79,431.79 J19.26@2616.79,350.8
LED_BLINK: J17.95 R176.1 | length 647.8
  Top Layer w8: v1(123,1079.65) J17.95@256.07,1079.65
  Int4(Signal) w8: v1(123,1079.65) 246.66,955.99 v1(586.5,955.99)
LoopSignal: RN3.3 U19.6 U19.7 | length 479.3
  Top Layer w10: U19.7@1690.83,1254.02 U19.6@1690.83,1204.02 v1(1740.62,1204.02)
  Int9(Signal) w10: v1(1740.62,1204.02) 1751.98,1192.67 1796.68,1192.67 1799.35,1190 2028.54,1190 2051.24,1212.7 v1(2053.86,1212.7)
  Bottom Layer w6: v1@2052.35,1211.19 v1(2053.86,1212.7)
  Bottom Layer w10: RN3.3@2008.19,1220.58 2043.53,1220.58 2051.41,1212.7 v1(2053.86,1212.7)
NetC9_1: C9.1 C10.1 J2.1 R210.1 | length 128.6
  Bottom Layer w50: J2.1@2943,2778 2946.93,2781.93 C9.1@2946.93,2905
NetC14_2: C14.2 C15.2 J2.3 R212.1 | length 203.1
  Bottom Layer w20: R212.1@2638.5,2665 2638.5,2711.06 2652.44,2725 C15.2@2656.38,2725
  Bottom Layer w50: J2.3@2595,2775 2603.07,2783.07 C14.2@2603.07,2905
NetC19_1: C19.1 R51.1 R60.2 RN7.3 U9.11 | length 1111.3
  Int2(Signal) w6: v1(1684.29,1566.1) 1716.6,1566.1 1728.2,1554.5 1728.2,1325.94 1769.2,1284.94 1769.2,1164.02 1781.52,1151.71 v1(1781.52,1126.09)
  Bottom Layer w6: RN7.3@1615.38,1615.05 1615.38,1590 1626.38,1579 1671.39,1579 v1(1684.29,1566.1) 1686.05,1564.34 1686.05,1511.35 1697.87,1499.53 1761.08,1499.53 1764.59,1503.04 C19.1@1764.59,1520.34 1764.59,1540.59 1783.95,1559.95 U9.11@1783.95,1586.4 ; v1(1639.97,976.72) 1643.91,976.72 1664.72,955.91 1706.69,955.91 1717.35,966.56 1717.35,1042.3 1781.52,1106.47 v1(1781.52,1126.09)
NetC20_2: C20.2 R50.1 R55.1 RN3.6 | length 547
  Int9(Signal) w8: v1(1699.79,1385.09) 1746.37,1385.09 1762.15,1400.87 1809.13,1400.87 v1(1905,1305)
  Bottom Layer w8: R55.1@1702.3,1428.76 R50.1@1702.3,1384.22 1746.3,1384.22 C20.2@1748.8,1381.72 ; v1(1905,1305) 1960,1305 1976.36,1288.64 1976.36,1243.3 1953.64,1220.58 RN3.6@1905.83,1220.58
NetC27_1: C27.1 R52.2 R58.2 U9.2 | length 311.5
  Int9(Signal) w6: v1(1931.42,1717.41) 1956.46,1692.38 2012.05,1692.38 v1(2037.08,1667.34)
  Bottom Layer w6: U9.2@1783.95,1696.64 1783.95,1725.94 1787.46,1729.45 1922.61,1729.45 1931.42,1720.64 v1(1931.42,1717.41)
NetC27_2: C27.2 R56.2 R59.2 U9.3 | length 293.7
  Int2(Signal) w6: v1(1931.42,1670.17) 1966.02,1670.17 1990.29,1694.43 2012.82,1694.43 v1(2037.08,1718.7)
  Bottom Layer w6: U9.3@1803.63,1696.64 1803.63,1713.09 1808,1717.45 1830.82,1717.45 1831.67,1716.6 1888.92,1716.6 1931.42,1674.11 v1(1931.42,1670.17)
NetC30_1: C30.1 R230.2 U13.4 | length 422.4
  Bottom Layer w8: C30.1@1814.38,1807 1807.35,1814.03 v1(1807.35,1915.35) 1807.35,1916.7 1825.7,1935.05 1827.05,1935.05 1849.84,1957.84 1891.11,1957.84
  Bottom Layer w10: 1891.11,1957.84 2024.16,1957.84 2051,1931 U13.4@2051,1893
NetC30_2: C30.2 R229.2 U13.1 | length 149.4
  Bottom Layer w10: C30.2@1857,1805 1863.56,1805 1880,1821.44 R229.2@1880,1856.38 ; R229.2@1881,1851.44 1914.17,1818.28 1948.14,1818.28 U13.1@1950.82,1815.6
NetC32_2: C32.2 C37.1 R229.1 R230.1 U15.10 | length 318.5
  Top Layer w8: U15.10@1803.63,1696.64 1803.63,1740.96 1826.89,1764.22 v1(1830.83,1764.22)
  Top Layer w10: R230.1@1852,1917 1857.56,1917 1869.08,1905.48 1878.15,1905.48 v1(1880,1903.62)
  Int2(Signal) w8: v1(1830.83,1764.22) 1880,1813.39 v1(1880,1903.62)
  Bottom Layer w8: C32.2@1835.97,1903.62 v1(1880,1903.62)
NetC35_2: C35.2 R62.2 RN2.2 U8.3 | length 254.4
  Top Layer w6: v1(1438.25,1429.1) 1453.37,1429.1 1461.09,1421.38 1461.09,1408.56 1475.09,1394.56 1475.09,1346.57 1466.8,1338.27 v1(1466.8,1334.57)
  Bottom Layer w6: v1(1438.25,1429.1) 1449.13,1439.98 1449.13,1475.63 1457.63,1484.13 1473.16,1484.13 RN2.2@1479.01,1489.99 ; C35.2@1466.57,1289.17 1466.57,1334.35 v1(1466.8,1334.57)
NetC36_1: C36.1 R89.1 RN6.3 U15.11 | length 437.5
  Top Layer w6: v1(1775.44,1764.22) 1783.95,1755.71 U15.11@1783.95,1696.64
  Int2(Signal) w6: v1(1675,1964) 1655.05,1944.05 1655.05,1844.95 1735.78,1764.22 v1(1775.44,1764.22)
  Bottom Layer w6: RN6.3@1640.97,1898.71 1640.97,1939.92 1651.7,1950.65 1661.65,1950.65 v1(1675,1964)
NetC38_1: C38.1 R91.2 R93.2 U15.2 | length 321.6
  Top Layer w8: U15.2@1783.95,1586.4 1783.95,1551.32 1814.93,1520.34 1932.5,1520.34 v1(1935.3,1517.55)
  Int9(Signal) w8: v1(1935.3,1517.55) 1964.37,1517.55 1988.47,1541.64 2012.45,1541.64 v1(2036.54,1565.74)
NetC38_2: C38.2 R92.2 R95.2 U15.3 | length 288.9
  Top Layer w8: U15.3@1803.63,1586.4 1803.63,1560.09 1808.32,1555.4 1884.97,1555.4 1898.57,1569 v1(1932.81,1569)
  Int2(Signal) w8: v1(1932.81,1569) 1959.92,1569 1985.24,1543.67 2012.35,1543.67 v1(2037.68,1518.35)
NetC39_1: C39.1 U22.13 | length 80.5
  Top Layer w6: U22.13@1995.44,735.82 2001.34,735.82 2028.89,708.28 C39.1@2064.51,708.28
NetC39_2: C39.2 C40.2 C41.2 R105.2 R106.2 U10.7 U25.2 U25.8 | length 2019.6
  Top Layer w6: v1(1751.34,676.81) 1751.34,736.2 1776.09,760.96 C40.2@1776.09,764.9 1776.09,815.37 C41.2@1776.42,815.69 ; v1(1984.53,984.03) 1984.53,1032.71 1990.17,1038.36 U10.7@2031.78,1038.36 ; v1(2232.48,1438.48) 2261.38,1467.38 U25.8@2261.38,1491.42 ; v1(2347.62,1651.36) 2348.3,1650.68 2348.3,1605.3 U25.2@2348.98,1604.61
  Top Layer w10: R106.2@2064.51,810.55 C39.2@2064.51,755.52 2097.5,755.52 2104.44,762.47 v1(2107.06,762.47)
  Int2(Signal) w6: v1(1984.53,984.03) 1984.53,948.47 2045.8,887.2 2045.8,845.13 2107.06,783.86 v1(2107.06,762.47)
  Int9(Signal) w6: v1(1751.34,676.81) 1839.22,676.81 1878.4,716 2060.59,716 v1(2107.06,762.47) ; v1(1984.53,984.03) 1984.53,1057.77 2125.91,1199.15 2125.91,1411.35 2155.39,1440.84 2230.13,1440.84 v1(2232.48,1438.48) ; v1@2232.48,1437.89 v1(2232.48,1438.48) ; v1(2347.62,1651.36) 2347.62,1588.54 2355.03,1581.13 2355.03,1522 2289.23,1456.2 2250.2,1456.2 v1(2232.48,1438.48)
NetC40_1: C40.1 U22.8 | length 77.3
  Top Layer w6: C40.1@1776.09,717.65 1821.75,717.65 1839.92,735.82 U22.8@1845.83,735.82
NetC41_1: C41.1 U22.5 | length 102.6
  Top Layer w8: C41.1@1776.42,862.93 1816.55,862.93 1845.83,833.66 U22.5@1845.83,812.6
NetC46_1: C46.1 U27.3 U28.6 | length 620.2
  Top Layer w6: v1(1213.28,1111.14) 1278.1,1111.14 1283.56,1116.6 U28.6@1283.56,1154.91 ; U27.3@1235.2,816.5 1276.52,816.5 1279.47,813.55 1279.62,813.55 v1(1296.35,796.81)
  Int2(Signal) w6: v1(1213.28,1111.14) 1194.43,1111.14 1187.38,1104.09 1187.38,976.01 1198.6,964.79 1198.6,894.57 v1(1296.35,796.81)
  Bottom Layer w6: C46.1@1245.28,778.11 1277.65,778.11 v1(1296.35,796.81)
NetC46_2: C46.2 U27.4 U28.5 | length 569.1
  Top Layer w6: v1(1206.22,1086.45) 1206.22,1089.52 1194.43,1101.31 1194.43,1126.47 1197.95,1129.99 1249.07,1129.99 1257.97,1138.88 U28.5@1257.97,1154.91 ; U27.4@1235.2,836.18 1280.92,836.18 1290.86,826.24 1301.06,826.24 v1(1303.28,824.02)
  Int2(Signal) w6: v1(1206.22,1086.45) 1208.84,1083.83 1208.84,1076.86 1209.61,1076.09 1209.61,970.74 1210.6,969.76 1210.6,907.86 1291.82,826.64 1300.67,826.64 v1(1303.28,824.02)
  Bottom Layer w6: C46.2@1245.28,825.36 1246.61,824.02 v1(1303.28,824.02)
NetC49_2: C49.2 C50.1 U28.2 U29.6 | length 331.2
  Top Layer w6: v1(900.76,1258.02) 902.14,1256.64 v1(952.03,1256.64) ; v1(1178.88,1264.87) 1178.88,1261.17 1188.05,1251.99 1188.05,1251.64 1192.29,1247.39 1216.67,1247.39 U28.2@1217.89,1246.17
  Int9(Signal) w6: v1(952.03,1256.64) 1166.95,1256.64 1175.18,1264.87 v1(1178.88,1264.87)
NetC51_1: C51.1 U29.5
  other v1: 905.09,1306.88
NetC52_1: C52.1 U27.6 U28.12 | length 680.9
  Top Layer w6: U27.6@1235.2,875.55 v1@1280.92,875.55 ; U28.12@1374.11,1271.76 1396.51,1271.76 1414.63,1289.88 v1(1414.63,1292.43)
  Int2(Signal) w6: v1(1288.43,875.55) 1237.44,926.54 1237.44,1080.77 1394.78,1238.11 1394.78,1272.58 v1(1414.63,1292.43)
  Bottom Layer w6: C52.1@1246.34,931.32 1246.34,927.38 1285.81,887.91 1285.81,878.17 v1(1288.43,875.55)
NetC52_2: C52.2 U27.5 U28.14 | length 758
  Top Layer w6: U27.5@1235.2,855.87 1285.53,855.87 1292.65,848.75 v1(1296.35,848.75) ; U28.14@1309.15,1311.83 1309.15,1356.26 v1(1311.41,1358.52)
  Int2(Signal) w6: v1(1296.35,848.75) 1293.74,851.37 1285.97,851.37 1225.44,911.9 1225.44,1096.64 1236.17,1107.38 1236.17,1283.28 v1(1311.41,1358.52)
  Bottom Layer w6: C52.2@1246.34,884.08 1246.34,880.14 1277.51,848.97 1296.14,848.97 v1(1296.35,848.75)
NetC53_2: C53.2 R119.2 U30.3 | length 681.4
  Bottom Layer w8: R119.2@1126.18,892.29 C53.2@1126.18,845.65 1127.97,843.86 1127.97,826.52 1229.7,724.79 1282.04,724.79 1315.1,691.73 1552.53,691.73 1558.39,697.59 1558.39,729.5 1542.81,745.08 1498.88,745.08 v1(1481.07,762.89) v1@1477.9,762.89
NetC56_1: C56.1 R123.2 U17.2 U30.1 | length 301.2
  Bottom Layer w6: U17.2@1366.9,913.57 1366.9,952.9 1385,971 1437.49,971 1441,967.49 1441,888 1460.34,868.66 1471.92,868.66 v1(1477.64,862.93) ; C56.1@1478,861 C56.1@1478,863.01
  Bottom Layer w12: C56.1@1478,863.01 1528.23,863.01 R123.2@1528.31,863.08
NetC56_2: C56.2 R123.1 U30.2 | length 50.7
  Bottom Layer w10: v1(1477.64,815.69) 1477.79,815.84 R123.1@1528.31,815.84
NetC57_2: C57.2 C58.1 R124.1 U31.10 | length 119.7
  Top Layer w6: v1(926.36,1386.85) 926.36,1436.1 928.08,1437.82 U31.10@946.9,1437.82
  Bottom Layer w8: v1(926.36,1386.85) C57.2@975.54,1386.85
NetC86_1: C86.1 C87.2 R132.2 R133.1 | length 77.6
  Int2(Signal) w8: v1(1174.34,1844.19) 1198.2,1820.33 1205.12,1820.33 v1(1230.56,1794.89)
  Bottom Layer w8: C87.2@1175.66,1846.81 C87.2@1176.31,1846.16
NetC87_1: C87.1 C88.2 R136.2 R137.1 | length 75.3
  Int9(Signal) w8: v1(1176.31,1796.35) 1221.91,1841.95 1229.61,1841.95 v1(1231.84,1844.19)
NetC90_1: C90.1 U36.3 | length 142.8
  Top Layer w8: U36.3@1001.76,1773.8 1052.52,1773.8 v1(1077.72,1748.6)
  Bottom Layer w8: C90.1@1028.85,1730.44 1059.34,1730.44 1077.5,1748.6 v1(1077.72,1748.6)
NetC91_1: C91.1 C92.2 C93.1 R138.1 U36.9 | length 219.4
  Top Layer w6: U36.9@936.8,1848.6 936.8,1868.39 943.85,1875.44 975.43,1875.44 988.14,1888.14 988.14,1903.35 v1(990.22,1905.44)
  Bottom Layer w10: R138.1@980.22,1790.44 981.6,1791.81 C93.1@981.6,1840.44 981.6,1861.59 993.64,1873.62 993.64,1902.02 v1(990.22,1905.44)
NetC94_1: C94.1 RN6.1 U35.1 U37.5 | length 761.4
  Top Layer w8: U37.5@1517.07,1785.5 1583.69,1785.5 C94.1@1597.62,1771.56 ; v1(1577,1964) 1577.7,1963.3 1605.06,1963.3 1619.43,1948.93 1619.43,1783.72 1614.75,1779.03 1605.43,1779.03 1597.62,1771.22 C94.1@1597.62,1767.63
  Bottom Layer w8: U35.1@1388.05,1800.26 1388.05,1847.31 1370.18,1865.19 1370.18,1908.57 1425.61,1964 1555.82,1964 ; v1(1577,1964) 1555.82,1964 ; RN6.1@1589.79,1898.71 1589.79,1908.53 1584.94,1913.39 1575.12,1913.39 1555.82,1932.69 1555.82,1964
NetC94_2: C94.2 RN6.2 U37.6 | length 267
  Top Layer w8: U37.6@1517.07,1805.18 1589.81,1805.18 1597.62,1813 1597.62,1942.68 v1(1596.84,1943.46)
  Bottom Layer w8: v1(1596.84,1943.46) 1596.84,1940.3 1610.53,1926.61 1610.53,1903.57 RN6.2@1615.38,1898.71
NetC95_1: C95.1 C96.2 R143.2 R144.1 | length 75.4
  Int2(Signal) w8: v1(1174.34,1746.04) 1215.42,1704.97 1229.61,1704.97 v1(1231.84,1702.73)
NetC96_1: C96.1 C97.2 R145.2 R146.1 | length 76.5
  Int9(Signal) w8: v1(1174.34,1702.73) 1217.93,1746.32 1229.61,1746.32 v1(1231.84,1748.55)
NetC98_1: C98.1 RN6.5 U37.8 | length 327.1
  Top Layer w6: C98.1@1452.71,1888.53 v1(1454.68,1888.53) 1456.65,1888.53 1471.8,1873.38 U37.8@1471.8,1830.77
  Bottom Layer w6: v1(1454.68,1888.53) 1484.73,1858.48 1505.05,1858.48 1520.53,1843 1635.44,1843 1660.71,1817.73 1660.71,1802.21 RN6.5@1666.57,1796.35
NetC98_2: C98.2 RN6.6 U37.7 | length 392.3
  Top Layer w8: U37.7@1491.48,1830.77 1491.48,1880.72 v1(1497.99,1887.22) 1499.29,1888.53 C98.2@1499.96,1888.53
  Bottom Layer w8: v1@1499.4,1884 1500.39,1884.99 1503.39,1884.99 1505.99,1882.38 1508.04,1882.38 1534.42,1856 1649.44,1856 1685.42,1820.02 1685.42,1772.68 1678.42,1765.68 1654.71,1765.68 1645.83,1774.55 1645.83,1791.49 RN6.6@1640.97,1796.35
NetC99_1: C99.1 U40.23 | length 107.1
  Top Layer w8: C99.1@1225.08,2290.51 1225.08,2290.43 1239.78,2275.73 U40.23@1326.05,2275.73
NetC110_1: C110.1 C111.1 C112.1 FB1.1 U41.10 U41.11 U41.12 U41.13 U41.14 U41.15 U41.27 | length 361.7
  Top Layer w10: U41.15@1862.33,2304.27 1902.68,2304.27 v1(1903.67,2303.29) ; U41.14@1869.22,2341.67 1901.7,2341.67 v1(1903.67,2343.64) ; U41.13@1873.59,2375.69 1873.59,2407.65 1912.69,2446.76 v1(1913.67,2446.76) ; U41.12@1905.64,2386.95 1905.64,2438.72 v1(1913.67,2446.76) ; U41.11@1925.32,2386.95 C112.1@1925.32,2441.01 ; U41.10@1945.01,2386.95 1945.01,2422.31 1926.31,2441.01 C112.1@1925.32,2441.01 ; v1(1913.67,2446.76) C112.1@1916.63,2449.71 C112.1@1925.32,2441.01
  other v1: 1929.26,2303.29 1929.26,2343.64 2131.51,2437.36
NetC113_1: C113.1 C114.1 C115.1 FB1.2 J11.1 R151.2 | length 493.2
  Top Layer w8: R151.2@1931.06,2068.7 1934.05,2065.7 v1@1934.05,2031
  Int5 (GND&PW) w10: v1(1933.98,2026.87) 1958.48,2051.37 1958.48,2166.17 2035.56,2243.25 2047.95,2243.25 v1(2129.38,2324.68)
  Bottom Layer w10: v1(2129.38,2324.68) 2131.51,2326.8 v1(2131.51,2392.09)
NetC120_2: C120.2 U41.21 | length 86.5
  Top Layer w10: C120.2@1883.39,2115.94 1883.39,2119.88 1904.84,2141.33 1909.69,2141.33 1925.32,2156.96 U41.21@1925.32,2182.22
NetC121_1: C121.1 U42.23 | length 207.5
  Top Layer w10: C121.1@849,2611.46 849.08,2611.38 924.26,2611.38 962.47,2573.16 U42.23@962.47,2495
NetC137_1: C137.1 R161.2 U43.7 | length 112.6
  Top Layer w10: U43.7@2409.43,2132.35 2429.31,2132.35 2435.17,2126.49 v1(2435.17,2042.03)
NetC140_1: C140.1 C141.1 R210.2 R211.1
NetC142_2: C142.2 C143.2 R212.2 R213.1 | length 89
  Bottom Layer w20: R212.2@2701.5,2665 2701.5,2616.65 2723.31,2594.84 C142.2@2723.31,2585
NetC151_1: C151.1 RN7.1 U37.23 U38.1 | length 414.3
  Top Layer w8: C151.1@1451.1,1624.36 1471.8,1645.05 U37.23@1471.8,1681.17
  Bottom Layer w8: U38.1@1386.17,1630.97 1438.84,1630.97 1453.23,1616.59 v1(1455.35,1616.59) 1490.12,1651.36 1513.63,1651.36 1523.59,1661.33 1564.04,1661.33 1567.07,1664.36 1655.46,1664.36 1666.57,1653.25 RN7.1@1666.57,1615.05
NetC151_2: C151.2 RN7.2 U37.24 | length 243.8
  Top Layer w8: U37.24@1491.48,1681.17 1491.48,1627.29 C151.2@1494.41,1624.36
  Bottom Layer w8: v1(1498.65,1616.59) 1529.39,1647.33 1569.84,1647.33 1570.68,1648.17 1636.29,1648.17 1640.97,1643.49 RN7.2@1640.97,1615.05
NetC152_1: C152.1 RN7.5 U37.2 | length 75
  Top Layer w6: U37.2@1517.07,1726.44 C152.1@1588.81,1726.44
  Bottom Layer w6: v1(1589,1720.36) 1589,1718.2 RN7.5@1589.79,1717.41
NetC152_2: C152.2 RN7.6 U37.1 | length 195.6
  Top Layer w8: U37.1@1517.07,1706.76 1541.54,1706.76 1553.58,1694.72 1553.58,1683.4 v1(1555.82,1681.17) 1558.98,1681.17 1565.06,1675.09 C152.2@1597.62,1675.09
  Bottom Layer w8: v1(1555.82,1681.17) 1557.7,1679.29 1609.93,1679.29 1615.38,1684.74 RN7.6@1615.38,1717.41
NetD1_2: D1.2 R39.2 R196.1 U5.2 U24.5 | length 2444.3
  Top Layer w10: U24.5@2410.99,1844.55 2411.07,1844.63 2448.63,1844.63 v1(2450,1846)
  Int2(Signal) w8: v1(2557.73,674.96) 2557.73,877.22 2566,885.49 2566,1710.97 2476.85,1800.11 2476.85,1816.55 2478.15,1817.85 v1(2450,1846) 2450,1939.03 2607.39,2096.42 2625.27,2096.42 2818.85,2290 2878,2290 v1@2881,2293
  Bottom Layer w8: v1@2883,2290 2933.76,2290 2985.01,2238.74 D1.2@2987.57,2238.74
  Bottom Layer w10: v1@2449,1847 2451,1847 2569,1965 U5.2@2710.75,1965
  Bottom Layer w20: D1.2@2987.57,2238.74 2988.63,2238.74 2989.38,2238 2989.38,2208.12 3014.5,2183 R39.2@3021,2183
  other v1: 2882,2290
NetD2_2: D2.2 R41.1 R195.1 U24.2 | length 1646.3
  Top Layer w8: U24.2@2410.99,1785.5 2438.43,1785.5 2438.59,1785.34 2458.22,1785.34 2467.66,1794.78 2479.98,1794.78 2493.53,1808.33 v1(2496.69,1808.33)
  Int2(Signal) w8: v1(2496.69,1808.33) 2498.93,1806.1 2498.93,1799.13 2580,1718.06 2580,697.68 v1(2601.72,675.96)
  Bottom Layer w8: v1(2496.69,1808.33) 2496.69,1805.17 2515.86,1786 2753.27,1786 2789.33,1749.94 2791.89,1749.94 2797.14,1744.69 2797.14,1700.86 R41.1@2799,1699
NetD3_2: D3.2 R43.2 R44.1 R193.1 RN1.1 U6.2 U24.12 | length 4420.1
  Top Layer w8: v1(2194.5,1824.81) 2194.56,1824.87 2212.62,1824.87 2212.78,1824.71 2233.1,1824.71 2233.25,1824.87 U24.12@2261.38,1824.87
  Int2(Signal) w8: v1(2194.5,1824.81) 2194.5,1886.5 2244.2,1936.2 2415.33,2107.33 2415.33,2370.33 v1(2432,2387) ; v1(2566,1837.86) 2606,1797.86 2606,1056.02 2710.14,951.87 2710.14,726.35 2699.14,715.34 v1(2699.14,675.96)
  Int9(Signal) w8: v1(2194.5,1824.81) 2194.6,1824.71 2288.6,1824.71 2365.71,1747.6 2489.68,1747.6 2519.6,1777.52 2519.6,1795.77 2549.51,1825.69 2550.66,1825.69 2562.84,1837.86 v1(2566,1837.86) ; v1(2432,2387) 2432,2419 2477.1,2464.1 2980.74,2464.1 3018.33,2426.5 3353.5,2426.5 RN1.1@3370,2410
  Bottom Layer w10: R44.1@3186.5,2335 3268.57,2335 3298.46,2305.12 3298.46,1933.95 3281.4,1916.89 3238.81,1916.89 3216,1939.7 U6.2@3216,1958.4
  Bottom Layer w20: D3.2@3095.59,2342.4 3172.6,2342.4 R44.1@3180,2335 3186.5,2335 3201.5,2350 3201.5,2356.5 3250.6,2405.6 RN1.1@3373,2405.6 ; RN1.1@3373,2415 R43.2@3450,2415
NetD4_1: D4.1 R42.2 R43.1 R194.1 RN1.2 U24.14 | length 3623.5
  Top Layer w6: v1(2198,1774) 2226.89,1774 2238.39,1785.5 U24.14@2261.38,1785.5
  Top Layer w20: D4.1@3231.34,2337.21 3234.21,2337.21 3234.4,2337.4 3331.16,2337.4 3362.96,2305.6 RN1.2@3373,2305.6
  Int2(Signal) w6: v1(2198,1774) 2225,1774 2240,1789 2240,1913.62 2432,2105.62 2432,2340 v1(2453,2361) ; v1(2557.73,1805.84) 2593,1770.57 2593,758.63 2648.84,702.79 v1(2648.84,675.96)
  Int9(Signal) w6: v1(2198,1774) 2246.49,1774 2287.49,1733 2508.45,1733 2557.73,1782.29 v1(2557.73,1805.84) ; v1(2453,2361) 2456.7,2361 2465.27,2369.57 2970.21,2369.57 2976.59,2363.19 3315.41,2363.19 3367,2311.6 RN1.2@3367,2306
  Bottom Layer w20: RN1.2@3373,2305.6 3383.04,2305.6 3413.85,2336.42 3446.22,2336.42 R43.1@3450,2340.2
  Bottom Layer w25: R43.1@3450,2340.2 3453.22,2340.2 3454.5,2338.92 3454.5,2285.1 R42.2@3459,2280.6
NetD5_3: D5.3 R53.2 R54.1 R65.2 | length 458.9
  Top Layer w6: v1(1797.36,1381.03) 1799.33,1383 R53.2@1799.33,1429.1
  Int9(Signal) w6: v1(1578.09,1255.13) 1688.38,1365.42 1781.75,1365.42 v1(1797.36,1381.03)
  Bottom Layer w6: v1(1578.09,1255.13) 1578.09,1359.99 1599.13,1381.03 R65.2@1603.06,1381.03
NetD8_2: D8.2 R176.2 | length 63.1
  Bottom Layer w12: v1(633.74,955.99) 633.74,918.66 650.5,901.9 v1(650.5,899.83)
NetJ1_1: J1.1 K2.4 TP2.1 | length 1313.3
  Top Layer w40: 3111,2115.94 3111,2611 3146,2646 3356.57,2646 3380,2669.43 J1.1@3380,2795
  Int2(Signal) w25: TP2.1@3204.53,2476.5 3390,2661.97 3390,2785 J1.1@3380,2795
NetJ3_1: J3.1 R32.2 R46.2 R47.2 | length 688.3
  Top Layer w10: v1(2931,2186.62) 2935.38,2191 R47.2@2997.38,2191
  Int9(Signal) w10: v1(2931,2186.62) 3308.38,2186.62 J3.1@3480,2015
NetJ3_2: J3.2 R31.2 R45.2 | length 146
  Int9(Signal) w8: v1(3350,1876.38) 3441.38,1876.38 J3.2@3480,1915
